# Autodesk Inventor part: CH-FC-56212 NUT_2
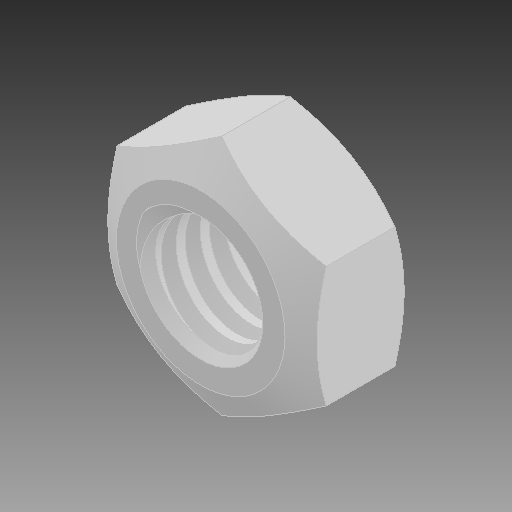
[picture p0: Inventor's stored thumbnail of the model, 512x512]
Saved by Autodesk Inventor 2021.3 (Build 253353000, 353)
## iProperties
Created: 2020-03
Part Number: CH-FC-56212 NUT_2
Material: Ogólny
Document SubType Name: Modeling
Designer: Przemyslaw Krecisz
Density: 1 g/cm^3
Appearance: Domyślna
Author: Przemyslaw Krecisz
Revision Number: ÈÎºÎ
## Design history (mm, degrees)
feature "¾µÏò1"
node "Bryła1"
